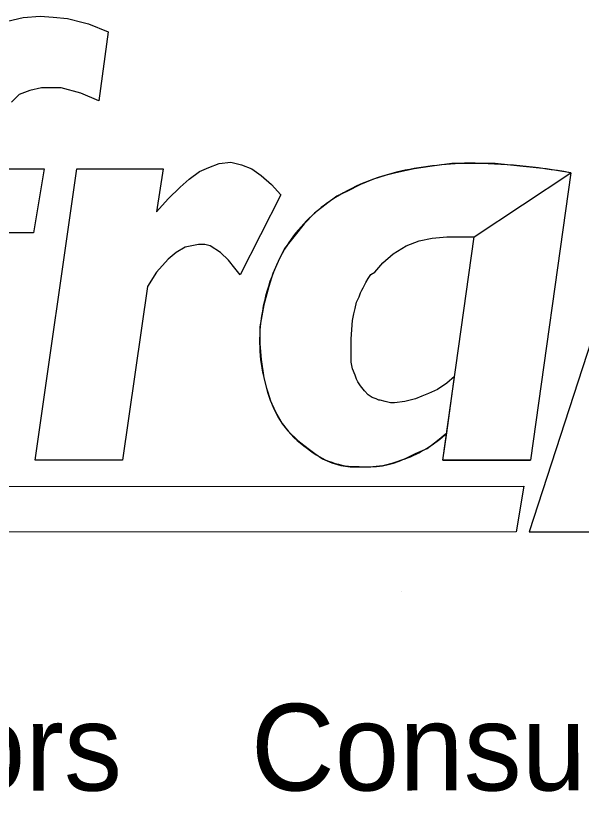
# Model space of a CAD drawing. Extents: x 2157704 to 2158404, y 1040586 to 1041166.
# Drawn here: x 2158052.77 to 2158065.76, y 1040689.71 to 1040708.1 of the extents above; entities that cross this region are included whole.
import ezdxf

# ---------------------------------------------------------------- set-up
doc = ezdxf.new("R2010")
doc.units = 0
doc.layers.add('SHT_B_Grid-Major-Line', color=7, linetype='Continuous')
doc.layers.add('SHT_B_North-Arrow', color=7, linetype='Continuous')

msp = doc.modelspace()

# ---------------------------------------------------------------- linework, layer by layer
at = {"layer": 'SHT_B_Grid-Major-Line'}
msp.add_line((2158062.569, 1040697.902), (2158062.658, 1040698.532), dxfattribs=at)
msp.add_line((2158062.569, 1040697.902), (2158062.658, 1040698.532), dxfattribs=at)
for points in [[(2158052.306, 1040707.92), (2158052.936, 1040708.07), (2158053.326, 1040708.1), (2158053.626, 1040708.071), (2158053.956, 1040708.041), (2158054.316, 1040707.951), (2158054.436, 1040707.921), (2158054.886, 1040707.741), (2158054.677, 1040706.151), (2158054.257, 1040706.331), (2158053.807, 1040706.451), (2158053.567, 1040706.451), (2158053.357, 1040706.45), (2158053.087, 1040706.39), (2158052.847, 1040706.3), (2158052.667, 1040706.12)], [(2158052.306, 1040707.92), (2158052.936, 1040708.07), (2158053.326, 1040708.1), (2158053.626, 1040708.071), (2158053.956, 1040708.041), (2158054.316, 1040707.951), (2158054.436, 1040707.921), (2158054.886, 1040707.741), (2158054.677, 1040706.151), (2158054.257, 1040706.331), (2158053.807, 1040706.451), (2158053.567, 1040706.451), (2158053.357, 1040706.45), (2158053.087, 1040706.39), (2158052.847, 1040706.3), (2158052.667, 1040706.12)], [(2158052.097, 1040704.59), (2158053.417, 1040704.591), (2158053.177, 1040703.12), (2158051.887, 1040703.12)], [(2158052.097, 1040704.59), (2158053.417, 1040704.591), (2158053.177, 1040703.12), (2158051.887, 1040703.12)], [(2158063.287, 1040703.033), (2158065.507, 1040704.503), (2158064.937, 1040704.593), (2158064.337, 1040704.653), (2158063.767, 1040704.713), (2158063.167, 1040704.713), (2158062.777, 1040704.713), (2158062.327, 1040704.652), (2158061.907, 1040704.592), (2158061.487, 1040704.502), (2158061.247, 1040704.442), (2158060.977, 1040704.352), (2158060.677, 1040704.232), (2158060.377, 1040704.082), (2158060.137, 1040703.962), (2158059.927, 1040703.812), (2158059.627, 1040703.572), (2158059.387, 1040703.332), (2158059.147, 1040703.032), (2158058.938, 1040702.762), (2158058.788, 1040702.462), (2158058.668, 1040702.192), (2158058.578, 1040701.892), (2158058.458, 1040701.472), (2158058.368, 1040700.962), (2158058.368, 1040700.572), (2158058.398, 1040700.212), (2158058.458, 1040699.792), (2158058.548, 1040699.462), (2158058.608, 1040699.282), (2158058.728, 1040699.012), (2158058.878, 1040698.742), (2158059.028, 1040698.562), (2158059.239, 1040698.352), (2158059.479, 1040698.172), (2158059.629, 1040698.052), (2158059.809, 1040697.932), (2158060.019, 1040697.842), (2158060.229, 1040697.782), (2158060.439, 1040697.752), (2158060.649, 1040697.752), (2158060.889, 1040697.752), (2158061.189, 1040697.782), (2158061.429, 1040697.842), (2158061.699, 1040697.932), (2158061.939, 1040698.052), (2158062.209, 1040698.172), (2158062.449, 1040698.352), (2158062.658, 1040698.532), (2158062.838, 1040699.823), (2158062.658, 1040699.672), (2158062.448, 1040699.522), (2158062.238, 1040699.432), (2158062.088, 1040699.372), (2158061.938, 1040699.312), (2158061.698, 1040699.252), (2158061.458, 1040699.222), (2158061.368, 1040699.222), (2158061.248, 1040699.252), (2158061.128, 1040699.282), (2158061.098, 1040699.282), (2158061.038, 1040699.312), (2158060.948, 1040699.342), (2158060.858, 1040699.402), (2158060.768, 1040699.492)], [(2158063.287, 1040703.033), (2158065.507, 1040704.503), (2158064.937, 1040704.593), (2158064.337, 1040704.653), (2158063.767, 1040704.713), (2158063.167, 1040704.713), (2158062.777, 1040704.713), (2158062.327, 1040704.652), (2158061.907, 1040704.592), (2158061.487, 1040704.502), (2158061.247, 1040704.442), (2158060.977, 1040704.352), (2158060.677, 1040704.232), (2158060.377, 1040704.082), (2158060.137, 1040703.962), (2158059.927, 1040703.812), (2158059.627, 1040703.572), (2158059.387, 1040703.332), (2158059.147, 1040703.032), (2158058.938, 1040702.762), (2158058.788, 1040702.462), (2158058.668, 1040702.192), (2158058.578, 1040701.892), (2158058.458, 1040701.472), (2158058.368, 1040700.962), (2158058.368, 1040700.572), (2158058.398, 1040700.212), (2158058.458, 1040699.792), (2158058.548, 1040699.462), (2158058.608, 1040699.282), (2158058.728, 1040699.012), (2158058.878, 1040698.742), (2158059.028, 1040698.562), (2158059.239, 1040698.352), (2158059.479, 1040698.172), (2158059.629, 1040698.052), (2158059.809, 1040697.932), (2158060.019, 1040697.842), (2158060.229, 1040697.782), (2158060.439, 1040697.752), (2158060.649, 1040697.752), (2158060.889, 1040697.752), (2158061.189, 1040697.782), (2158061.429, 1040697.842), (2158061.699, 1040697.932), (2158061.939, 1040698.052), (2158062.209, 1040698.172), (2158062.449, 1040698.352), (2158062.658, 1040698.532), (2158062.838, 1040699.823), (2158062.658, 1040699.672), (2158062.448, 1040699.522), (2158062.238, 1040699.432), (2158062.088, 1040699.372), (2158061.938, 1040699.312), (2158061.698, 1040699.252), (2158061.458, 1040699.222), (2158061.368, 1040699.222), (2158061.248, 1040699.252), (2158061.128, 1040699.282), (2158061.098, 1040699.282), (2158061.038, 1040699.312), (2158060.948, 1040699.342), (2158060.858, 1040699.402), (2158060.768, 1040699.492)], [(2158065.507, 1040704.503), (2158064.579, 1040697.903), (2158062.569, 1040697.902), (2158064.579, 1040697.903)], [(2158065.507, 1040704.503), (2158064.579, 1040697.903), (2158062.569, 1040697.902), (2158064.579, 1040697.903)], [(2158060.768, 1040699.492), (2158060.678, 1040699.612), (2158060.618, 1040699.702), (2158060.588, 1040699.762), (2158060.558, 1040699.852), (2158060.498, 1040700.002), (2158060.468, 1040700.152), (2158060.468, 1040700.242), (2158060.468, 1040700.692), (2158060.498, 1040701.112), (2158060.528, 1040701.262), (2158060.558, 1040701.382), (2158060.588, 1040701.532), (2158060.648, 1040701.652), (2158060.678, 1040701.742), (2158060.708, 1040701.802), (2158060.738, 1040701.862), (2158060.798, 1040701.982), (2158060.858, 1040702.072), (2158060.918, 1040702.162), (2158061.008, 1040702.222), (2158061.188, 1040702.432), (2158061.428, 1040702.642), (2158061.728, 1040702.822), (2158062.028, 1040702.942), (2158062.327, 1040703.002), (2158062.657, 1040703.032), (2158063.287, 1040703.033)], [(2158060.768, 1040699.492), (2158060.678, 1040699.612), (2158060.618, 1040699.702), (2158060.588, 1040699.762), (2158060.558, 1040699.852), (2158060.498, 1040700.002), (2158060.468, 1040700.152), (2158060.468, 1040700.242), (2158060.468, 1040700.692), (2158060.498, 1040701.112), (2158060.528, 1040701.262), (2158060.558, 1040701.382), (2158060.588, 1040701.532), (2158060.648, 1040701.652), (2158060.678, 1040701.742), (2158060.708, 1040701.802), (2158060.738, 1040701.862), (2158060.798, 1040701.982), (2158060.858, 1040702.072), (2158060.918, 1040702.162), (2158061.008, 1040702.222), (2158061.188, 1040702.432), (2158061.428, 1040702.642), (2158061.728, 1040702.822), (2158062.028, 1040702.942), (2158062.327, 1040703.002), (2158062.657, 1040703.032), (2158063.287, 1040703.033)], [(2158051.049, 1040697.3), (2158064.429, 1040697.303), (2158064.249, 1040696.253), (2158050.899, 1040696.25)], [(2158051.049, 1040697.3), (2158064.429, 1040697.303), (2158064.249, 1040696.253), (2158050.899, 1040696.25)]]:
    msp.add_lwpolyline(points, dxfattribs=at)
for points in [[(2158064.549, 1040696.253), (2158066.739, 1040696.253), (2158068.928, 1040702.944), (2158070.579, 1040696.254), (2158072.019, 1040696.255), (2158075.558, 1040702.705), (2158075.949, 1040696.255), (2158078.019, 1040696.256), (2158077.417, 1040706.306), (2158075.167, 1040706.305), (2158071.748, 1040700.094), (2158070.217, 1040706.304), (2158067.817, 1040706.304)], [(2158064.549, 1040696.253), (2158066.739, 1040696.253), (2158068.928, 1040702.944), (2158070.579, 1040696.254), (2158072.019, 1040696.255), (2158075.558, 1040702.705), (2158075.949, 1040696.255), (2158078.019, 1040696.256), (2158077.417, 1040706.306), (2158075.167, 1040706.305), (2158071.748, 1040700.094), (2158070.217, 1040706.304), (2158067.817, 1040706.304)], [(2158054.167, 1040704.591), (2158056.147, 1040704.591), (2158055.997, 1040703.601), (2158056.267, 1040703.901), (2158056.537, 1040704.171), (2158056.747, 1040704.351), (2158056.987, 1040704.531), (2158057.197, 1040704.621), (2158057.437, 1040704.711), (2158057.707, 1040704.741), (2158057.947, 1040704.681), (2158058.187, 1040704.592), (2158058.397, 1040704.442), (2158058.637, 1040704.232), (2158058.847, 1040703.992), (2158057.918, 1040702.161), (2158057.798, 1040702.311), (2158057.648, 1040702.491), (2158057.468, 1040702.671), (2158057.228, 1040702.821), (2158057.108, 1040702.851), (2158056.958, 1040702.851), (2158056.808, 1040702.821), (2158056.658, 1040702.791), (2158056.448, 1040702.671), (2158056.268, 1040702.521), (2158055.998, 1040702.221), (2158055.788, 1040701.891), (2158055.219, 1040697.901), (2158053.209, 1040697.9)], [(2158054.167, 1040704.591), (2158056.147, 1040704.591), (2158055.997, 1040703.601), (2158056.267, 1040703.901), (2158056.537, 1040704.171), (2158056.747, 1040704.351), (2158056.987, 1040704.531), (2158057.197, 1040704.621), (2158057.437, 1040704.711), (2158057.707, 1040704.741), (2158057.947, 1040704.681), (2158058.187, 1040704.592), (2158058.397, 1040704.442), (2158058.637, 1040704.232), (2158058.847, 1040703.992), (2158057.918, 1040702.161), (2158057.798, 1040702.311), (2158057.648, 1040702.491), (2158057.468, 1040702.671), (2158057.228, 1040702.821), (2158057.108, 1040702.851), (2158056.958, 1040702.851), (2158056.808, 1040702.821), (2158056.658, 1040702.791), (2158056.448, 1040702.671), (2158056.268, 1040702.521), (2158055.998, 1040702.221), (2158055.788, 1040701.891), (2158055.219, 1040697.901), (2158053.209, 1040697.9)], [(2158063.287, 1040703.033), (2158065.507, 1040704.503), (2158064.579, 1040697.903), (2158062.569, 1040697.902)], [(2158063.287, 1040703.033), (2158065.507, 1040704.503), (2158064.579, 1040697.903), (2158062.569, 1040697.902)]]:
    msp.add_lwpolyline(points, close=True, dxfattribs=at)
for centre, radius, start, end in [((2158063.37, 1040696.348), 8.376, 91.3825, 102.8864), ((2158063.37, 1040696.348), 8.376, 91.3825, 102.8864), ((2158063.003, 1040690.551), 14.171, 79.8949, 89.333), ((2158063.003, 1040690.551), 14.171, 79.8949, 89.333), ((2158062.555, 1040700.017), 4.617, 103.1881, 124.7438), ((2158062.555, 1040700.017), 4.617, 103.1881, 124.7438), ((2158062.017, 1040700.88), 3.602, 125.534, 148.7543), ((2158062.017, 1040700.88), 3.602, 125.534, 148.7543), ((2158062.795, 1040700.559), 4.435, 150.4218, 174.6396), ((2158062.795, 1040700.559), 4.435, 150.4218, 174.6396), ((2158062.009, 1040700.629), 3.646, 174.5811, 198.676), ((2158062.009, 1040700.629), 3.646, 174.5811, 198.676), ((2158060.69, 1040699.998), 2.201, 194.1052, 236.1864), ((2158060.69, 1040699.998), 2.201, 194.1052, 236.1864), ((2158060.665, 1040700.696), 2.951, 290.3221, 312.6068), ((2158060.665, 1040700.696), 2.951, 290.3221, 312.6068), ((2158060.609, 1040699.532), 1.779, 229.9908, 271.2799), ((2158060.609, 1040699.532), 1.779, 229.9908, 271.2799), ((2158060.832, 1040699.842), 2.096, 264.984, 294.153), ((2158060.832, 1040699.842), 2.096, 264.984, 294.153)]:
    msp.add_arc(centre, radius, start, end, dxfattribs=at)
at = {"layer": 'SHT_B_North-Arrow'}
msp.add_line((2158061.628, 1040694.885), (2158061.628, 1040694.885), dxfattribs=at)
msp.add_line((2158061.628, 1040694.885), (2158061.628, 1040694.885), dxfattribs=at)

# ---------------------------------------------------------------- texts
at = {"layer": 'SHT_B_Grid-Major-Line'}
msp.add_text('Utility Locators    Surveyors    Consulting Engineers', height=1.9908, rotation=0.0124, dxfattribs=at).set_placement((2158022.806, 1040690.309))
msp.add_text('Utility Locators    Surveyors    Consulting Engineers', height=1.9908, rotation=0.0124, dxfattribs=at).set_placement((2158022.806, 1040690.309))

doc.saveas('drawing.dxf')
